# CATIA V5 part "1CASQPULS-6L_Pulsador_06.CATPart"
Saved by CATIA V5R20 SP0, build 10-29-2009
Part number: 1CASQPULS-6L_Pulsador_06
Revision: ANY
Definition: UNKNOWN
Nomenclature: 1CASQPULS-6L_Pulsador_06
Source: Unknown
Bounding box of the stored display mesh (mm): x -6.63 to 6.63, y 0 to 15.3, z -6.8 to 6.8
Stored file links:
  C:\Users\Utente\Desktop\IO LAVORO\3D X SITO CF\CUMSA\3D files AE\AE 062430\1CASQPULS-6L_Pulsador_06.CATPart
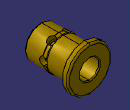
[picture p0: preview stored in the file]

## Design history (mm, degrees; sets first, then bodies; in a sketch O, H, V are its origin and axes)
Body1 "MatrizC1" (main body)
  Solid1: solid without history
